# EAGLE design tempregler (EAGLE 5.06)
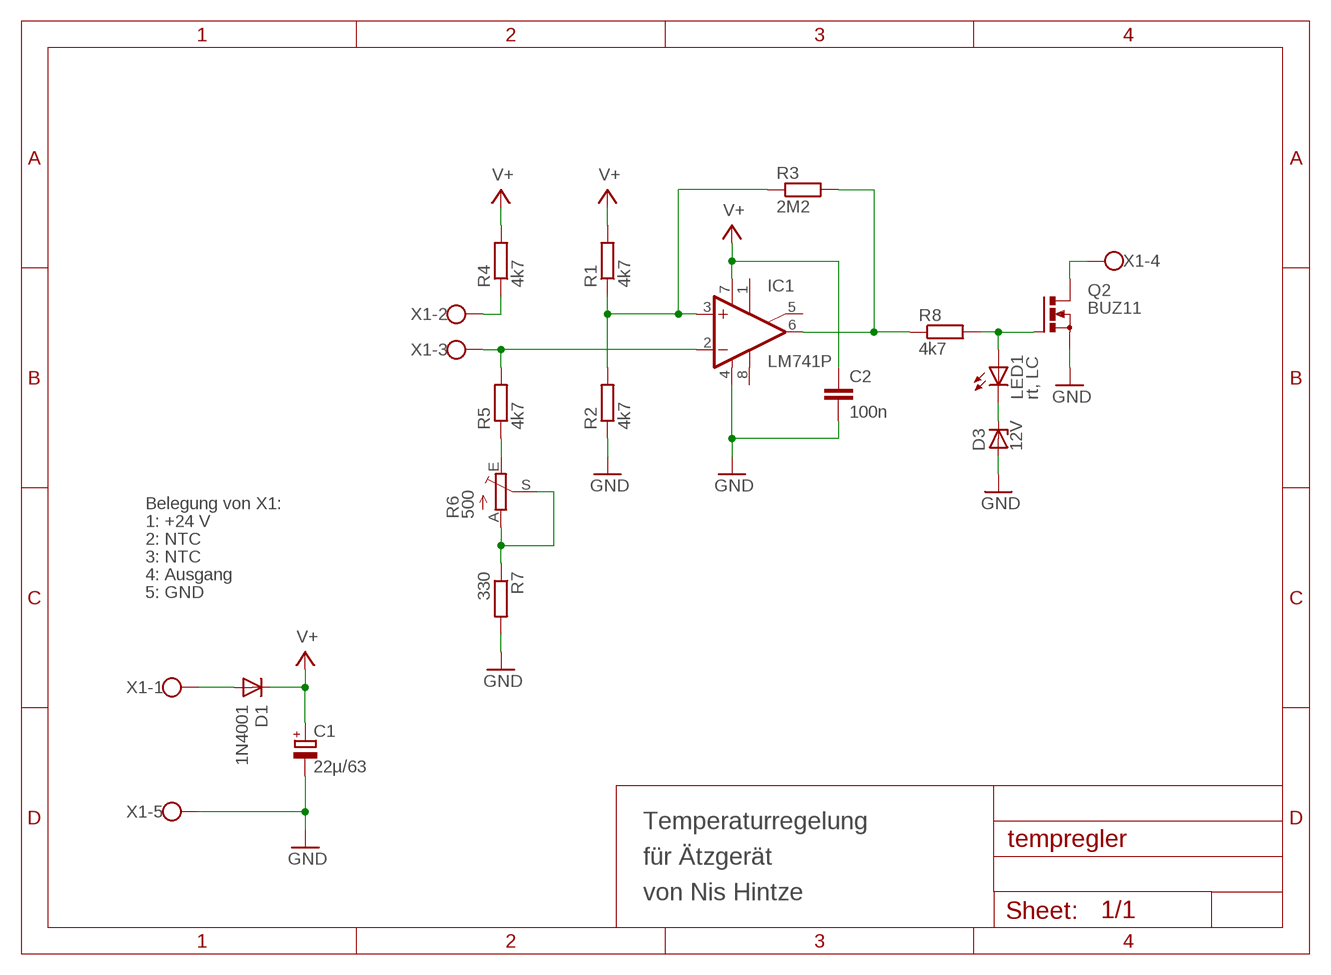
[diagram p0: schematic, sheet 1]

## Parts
C1  22µ/63  CPOL-EUE2.5-6  [E2,5-6]
C2  100n  C-EUC0805  [C0805]
D1  1N4001  1N4004  [DO41-10]
D3  12V  ZPD  [DO35Z10]
IC1  LM741P  [DIL08]
LED1  rt, LC  LED3MM  [LED3MM]
Q2  BUZ11  BUZ11BH  [TO220BH]
R1  4k7  R-EU_0207/10  [0207/10]
R2  4k7  R-EU_0207/5V  [0207/5V]
R3  2M2  R-EU_0207/10  [0207/10]
R4  4k7  R-EU_0207/10  [0207/10]
R5  4k7  R-EU_0207/10  [0207/10]
R6  500  TRIM_EU-S64W  [S64W]
R7  330  R-EU_0207/2V  [0207/2V]
R8  4k7  R-EU_0207/10  [0207/10]
X1  W237-05P  [W237-5P]

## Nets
GND: C1.- C2.2 D3.A IC1.4(V-) Q2.S R2.1 R7.2 X1.5
N$1: IC1.3(+IN) R1.1 R2.2 R3.1
N$2: D1.A X1.1
N$3: IC1.2(-IN) R5.2 X1.3
N$4: R5.1 R6.E
N$5: R4.1 X1.2
N$6: IC1.6(OUT) R3.2 R8.1
N$7: R6.A R6.S R7.1
N$8: LED1.A Q2.G R8.2
N$9: D3.C LED1.K(C)
N$10: Q2.D X1.4
V+: C1.+ C2.1 D1.C IC1.7(V+) R1.2 R4.2
Unconnected: IC1.1(ON1) IC1.5(ON2) IC1.8(OPT)

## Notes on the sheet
- Belegung von X1:
- 1: +24 V
- 2: NTC
- 3: NTC
- 4: Ausgang
- 5: GND
- Temperaturregelung
- für Ätzgerät
- von Nis Hintze

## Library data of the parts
C1 = nh_rcl:CPOL-EU: POLARIZED CAPACITOR, European symbol
C2 = nh_rcl:C-EU: CAPACITOR, European symbol
D1 = diode:1N4004: DIODE
D3 = nh_diode:ZPD: Z DIODE
IC1 = linear:*741: OP AMP
LED1 = nh_led:LED: LED
Q2 = transistor-power:BUZ11: N-CHANNEL MOS FET
R1-R5 R7 R8 = nh_rcl:R-EU_: RESISTOR, European symbol
R6 = nh_pot:TRIM_EU-: POTENTIOMETER
X1 = con-wago-508:W237-05P: WAGO SREW CLAMP

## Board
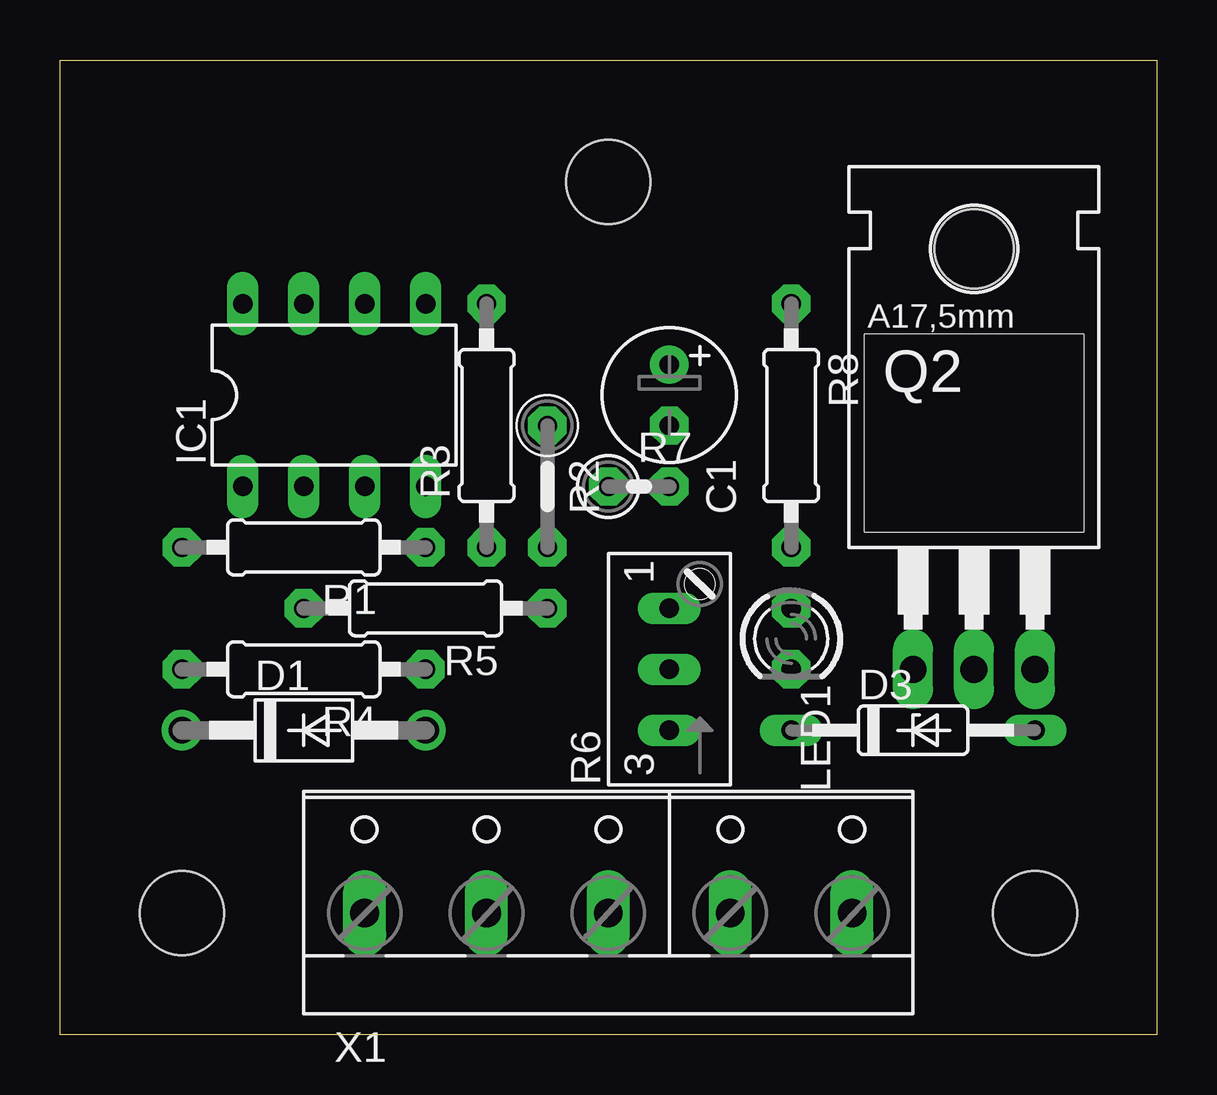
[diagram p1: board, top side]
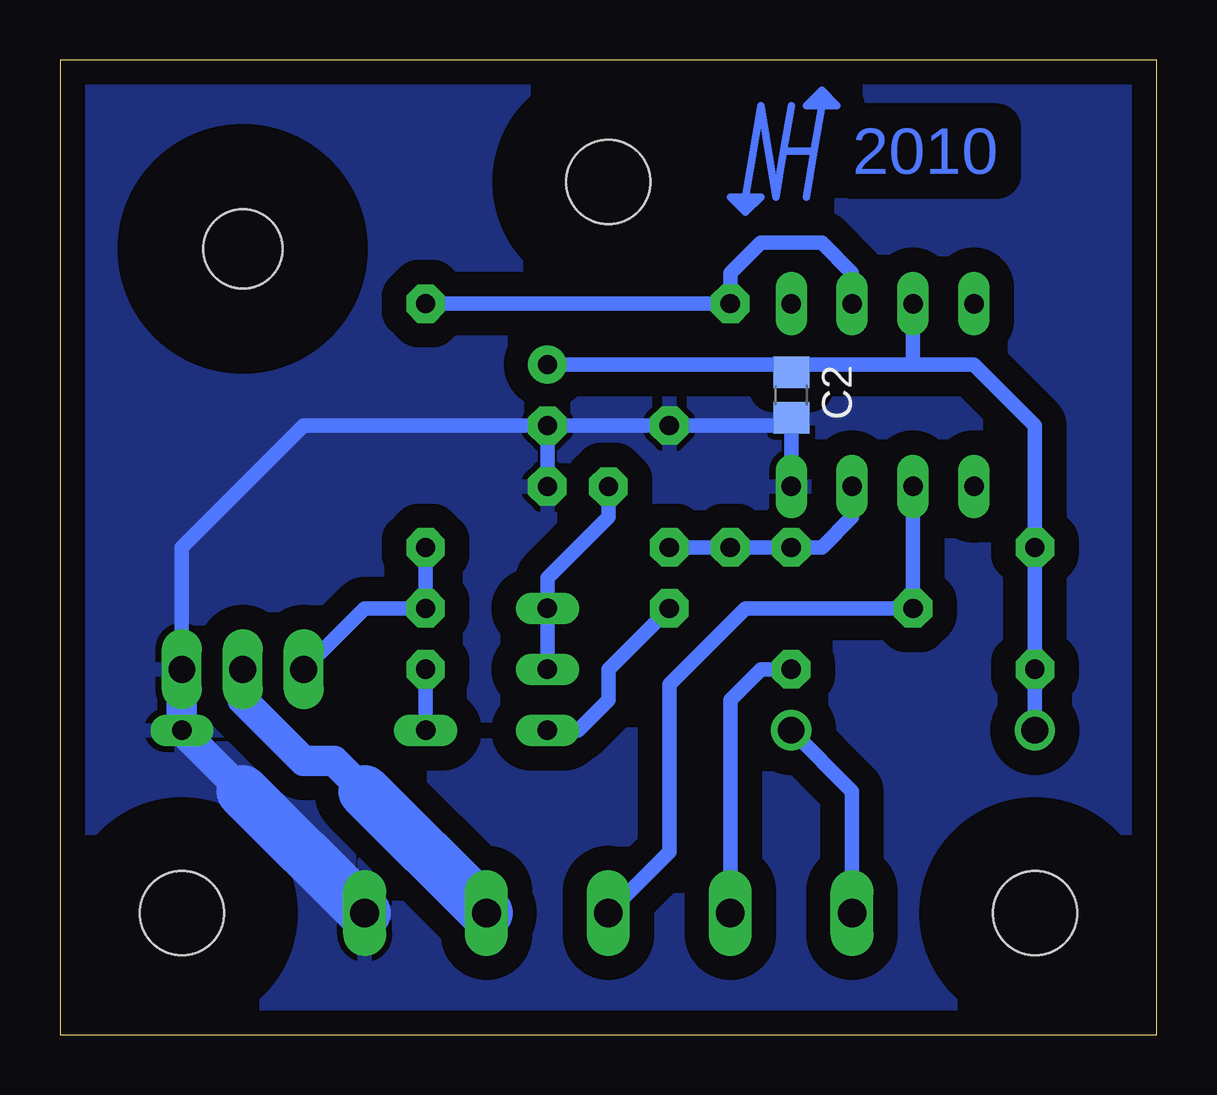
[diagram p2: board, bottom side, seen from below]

Size 45.72 x 40.64 mm. Coordinates in mm from the lower left corner, seen from the top.
Outline: 0,40.64 45.72,40.64 45.72,0 0,0 0,40.64
Copper layers (1*16): Top 0.035mm / dielectric 1.5mm / Bottom 0.035mm
Design rules "default": minimum track width 10mil, minimum drill 24mil, track to track 8mil, track to pad 8mil, pad to pad 8mil, via to via 8mil, smd to smd 8mil, copper to edge 40mil, drill to drill 8mil, minimum pad ring 10mil, minimum via ring 8mil, stop-mask expansion 4mil, vias tented up to drill 0mil, thermal gap 10mil
Holes 3.5 mm at 5.08,5.08 40.64,5.08 22.86,35.56
bRestrict: area 1.3,1.3 to 8.9,8.9; area 36.8,1.3 to 44.5,8.9; area 19.1,31.8 to 26.7,39.4

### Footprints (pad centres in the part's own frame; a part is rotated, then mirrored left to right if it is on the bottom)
E2,5-6 = drill 0.8 pad 1.6 round: + -1.27,0 | drill 0.8 pad 1.6 octagon: - 1.27,0
C0805 = smd 1.3 x 1.5: 1 -0.95,0; 2 0.95,0
DO41-10 = drill 1.118 round: A 5.08,0; C -5.08,0
DO35Z10 = drill 0.813 long: A 5.08,0; C -5.08,0
DIL08 = drill 0.813 long: 1 -3.81,-3.81; 2 -1.27,-3.81; 3 1.27,-3.81; 4 3.81,-3.81; 5 3.81,3.81; 6 1.27,3.81; 7 -1.27,3.81; 8 -3.81,3.81
LED3MM = drill 0.8 pad 1.6 octagon: A -1.27,0; K 1.27,0
TO220BH = drill 1.118 long: D 0,-6.35; G -2.54,-6.35; S 2.54,-6.35 | hole 3.302: 0,11.176
0207/10 = drill 0.8 pad 1.6 octagon: 1 -5.08,0; 2 5.08,0
0207/5V = drill 0.8 pad 1.6 octagon: 1 -2.54,0; 2 2.54,0
S64W = drill 0.813 long: A 2.54,1.27; E -2.54,1.27; S 0,1.27
0207/2V = drill 0.8 pad 1.6 octagon: 1 -1.27,0; 2 1.27,0
W237-5P = drill 1.194 long: 1 -10.16,-0.635; 2 -5.08,-0.635; 3 0,-0.635; 4 5.08,-0.635; 5 10.16,-0.635

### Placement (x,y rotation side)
C1  25.4,26.67 270 top
C2  15.24,26.67 270 bottom
D1  10.16,12.7 0 top
D3  35.56,12.7 0 top
IC1  11.43,26.67 0 top
LED1  30.48,16.51 270 top
Q2  38.1,21.59 0 top
R1  10.16,20.32 180 top
R2  20.32,22.86 270 top
R3  17.78,25.4 90 top
R4  10.16,15.24 180 top
R5  15.24,17.78 180 top
R6  26.67,15.24 90 top
R7  24.13,22.86 0 top
R8  30.48,25.4 270 top
X1  22.86,5.71 0 top

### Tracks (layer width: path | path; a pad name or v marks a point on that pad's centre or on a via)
GND
  Bottom 0.61: 15.24,25.4 R2.1 C1.- | 15.24,25.4 IC1.4 | 15.24,25.4 C2.2 | Q2.S 40.64,20.32 35.56,25.4 C1.- | C1.- R7.2
  Bottom 1.27: 38.1,10.16 D3.A Q2.S
  Bottom 2.184: X1.5 38.1,10.16
  pour Bottom (isolate 1.016): 0,40.64 45.72,40.64 45.72,0 0,0
N$1
  Bottom 0.61: IC1.3 12.7,21.59 13.97,20.32 R1.1 R3.1 R2.2
N$2
  Bottom 0.61: X1.1 12.7,10.16 D1.A
N$3
  Bottom 0.61: IC1.2 R5.2 17.14,17.78 20.32,14.61 20.32,7.62 X1.3
N$4
  Bottom 0.61: R6.E 24.13,12.7 22.86,13.97 22.86,15.24 R5.1
N$5
  Bottom 0.61: X1.2 17.78,13.97 16.51,15.24 R4.1
N$6
  Bottom 0.61: IC1.6 12.7,31.75 13.97,33.02 16.51,33.02 17.78,31.75 R3.2 R8.1
N$7
  Bottom 0.61: R6.S R6.A 25.4,19.05 22.86,21.59 R7.1
N$8
  Bottom 0.61: Q2.G 33.02,17.78 LED1.A R8.2
N$9
  Bottom 0.61: D3.C LED1.K
N$10
  Bottom 1.27: 33.02,10.16 34.29,11.43 35.56,11.43 38.1,13.97 Q2.D
  Bottom 2.184: X1.4 33.02,10.16
N$25
  Bottom 0.305: 17.14,34.92 16.51,38.73 15.88,34.92 15.56,36.83 | 15.56,36.83 15.24,38.73 | 14.29,36.83 15.56,36.83 | 14.29,36.83 13.97,38.73 | 14.61,34.92 14.29,36.83 | 17.14,34.92 17.78,34.92 | 17.78,34.92 17.14,34.29 | 16.51,34.92 17.14,34.29 | 17.14,34.92 16.51,34.92 | 13.97,38.73 14.61,38.73 | 14.61,38.73 13.97,39.37 | 13.34,38.73 13.97,39.37 | 13.97,38.73 13.34,38.73 | 13.97,38.73 13.97,39.05 | 13.97,39.05 13.97,39.37 | 17.14,34.92 17.14,34.61 | 17.14,34.61 17.14,34.29 | 13.34,38.73 13.97,39.05 | 14.61,38.73 13.97,39.05 | 16.51,34.92 17.14,34.61 | 17.78,34.92 17.14,34.61
V+
  Bottom 0.61: 15.24,27.94 C2.1 | 10.16,27.94 15.24,27.94 | 10.16,27.94 IC1.7 | 10.16,27.94 7.62,27.94 5.08,25.4 R1.2 R4.2 D1.C | 15.24,27.94 C1.+

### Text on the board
Bottom: 2010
